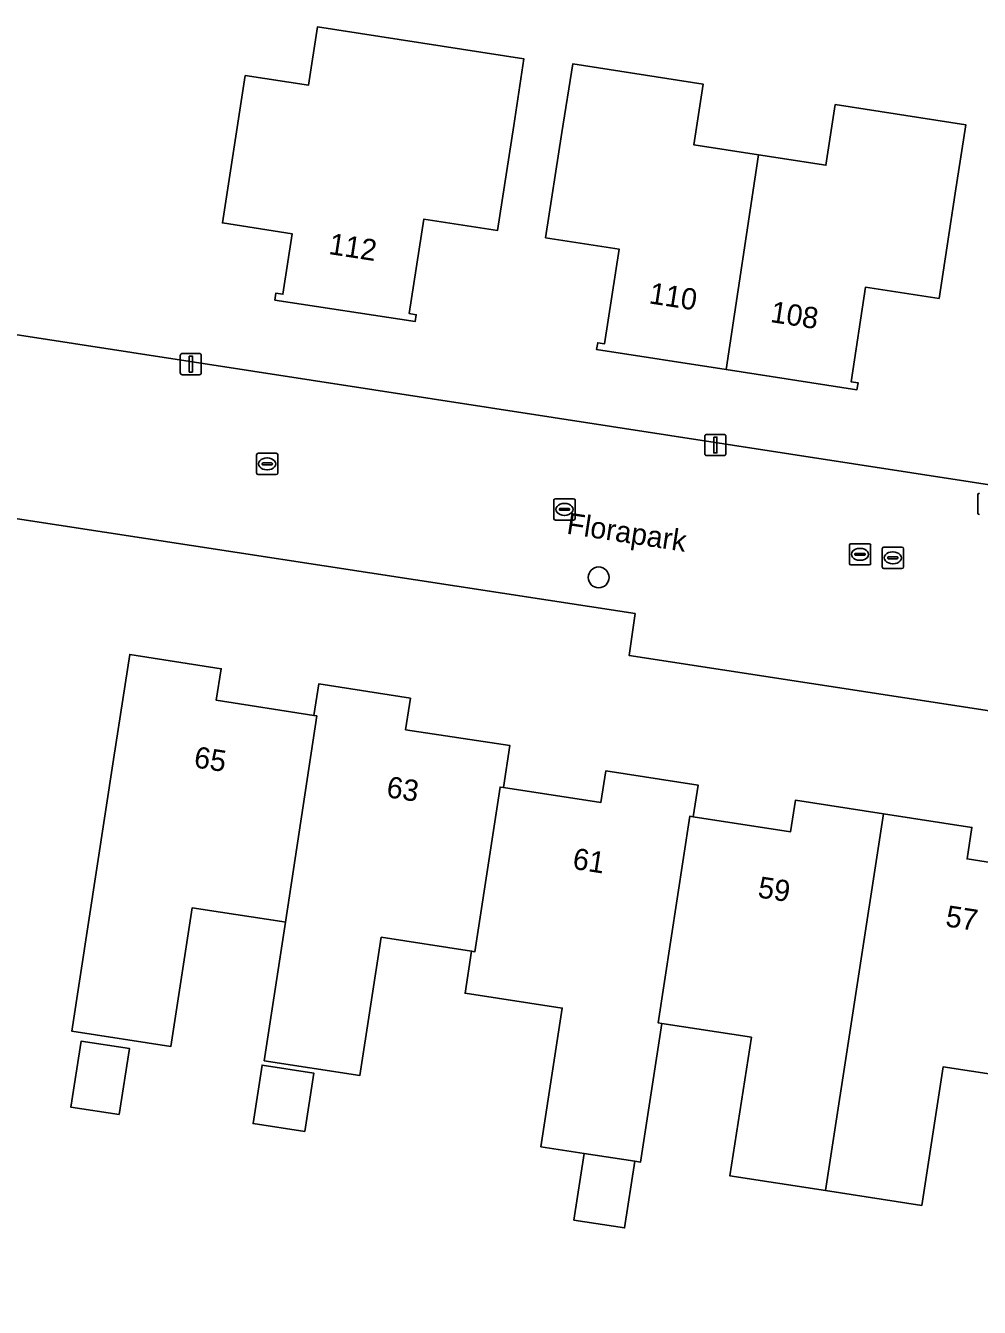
# Model space of a CAD drawing. Extents: x 161483 to 162250, y 379484 to 380833.
# Drawn here: x 161829.9 to 161874.7, y 380682.4 to 380742.6 of the extents above; entities that cross this region are included whole.
import ezdxf

# ---------------------------------------------------------------- set-up
doc = ezdxf.new("R2010")
doc.units = 0
for name, color, linetype in [('IMGEO_Boom', 7, 'Continuous'), ('IMGEO_Brandkraan', 7, 'Continuous'), ('IMGEO_Erf', 7, 'Continuous'), ('IMGEO_Kolk', 7, 'Continuous'), ('IMGEO_Lichtmast', 7, 'Continuous'), ('IMGEO_Openbare_ruimte_label', 7, 'Continuous'), ('IMGEO_Pand', 7, 'Continuous'), ('IMGEO_Pand_nummerreeks', 7, 'Continuous'), ('IMGEO_Rijbaan_lokaal_open', 7, 'Continuous'), ('IMGEO_Rioolput', 7, 'Continuous')]:
    doc.layers.add(name, color=color, linetype=linetype)

msp = doc.modelspace()

# ---------------------------------------------------------------- linework, layer by layer
at = {"layer": 'IMGEO_Boom'}
msp.add_circle((161856.794, 380716.676), 0.489, dxfattribs=at)
at = {"layer": 'IMGEO_Brandkraan'}
msp.add_line((161874.599, 380719.698), (161874.599, 380720.55), dxfattribs=at)
msp.add_lwpolyline([(161874.599, 380719.698), (161874.599, 380720.55)], dxfattribs=at)
for centre, start, end in [((161874.676, 380720.548), 91.55205, 178.44795), ((161874.676, 380720.548), 91.55205, 178.44795), ((161874.676, 380719.7), 181.55205, 268.44795), ((161874.676, 380719.7), 181.55205, 268.44795)]:
    msp.add_arc(centre, 0.0765, start, end, dxfattribs=at)
at = {"layer": 'IMGEO_Erf'}
for points in [[(161809.687, 380750), (161806.838, 380731.553), (161922.038, 380713.794), (161929.59, 380712.634), (161938.583, 380711.252), (161943.256, 380741.795), (161945.58, 380741.467)], [(161914.036, 380681.642), (161914.958, 380687.646), (161916.662, 380687.385), (161918.051, 380696.418), (161918.693, 380696.319), (161919.171, 380699.432), (161919.795, 380699.336), (161919.961, 380700.418), (161920.72, 380705.36), (161884.401, 380710.951), (161884.124, 380709.027), (161858.224, 380713.01), (161858.506, 380714.977), (161825.187, 380720.083)], [(161877.172, 380693.042), (161872.97, 380693.69), (161871.967, 380687.18), (161867.449, 380687.876), (161862.96, 380688.567), (161863.964, 380695.078), (161859.761, 380695.725), (161858.758, 380689.215), (161858.494, 380689.256), (161858.011, 380686.123), (161855.627, 380686.491), (161856.11, 380689.623), (161854.083, 380689.936), (161855.086, 380696.446), (161850.519, 380697.15), (161850.823, 380699.123), (161846.581, 380699.776), (161845.581, 380693.286), (161841.085, 380693.978), (161842.076, 380700.491), (161841.918, 380700.515), (161839.026, 380700.96), (161837.705, 380701.164), (161836.703, 380694.653), (161832.047, 380695.371), (161834.009, 380708.119), (161834.77, 380713.06), (161839.064, 380712.388), (161838.833, 380710.907), (161843.414, 380710.191), (161843.645, 380711.672), (161847.95, 380711), (161847.725, 380709.521), (161852.626, 380708.776), (161852.326, 380706.804), (161856.901, 380706.108), (161857.13, 380707.59), (161861.46, 380706.92), (161861.236, 380705.438), (161865.808, 380704.732), (161866.03, 380706.21), (161870.174, 380705.572), (161874.322, 380704.933), (161874.093, 380703.452), (161878.665, 380702.745)]]:
    msp.add_lwpolyline(points, dxfattribs=at)
for points in [[(161852.036, 380732.962), (161848.579, 380733.497), (161847.896, 380729.062), (161848.222, 380729.012), (161848.172, 380728.686), (161841.584, 380729.7), (161841.634, 380730.026), (161841.96, 380729.976), (161842.396, 380732.811), (161839.12, 380733.319), (161840.194, 380740.244), (161843.159, 380739.785), (161843.585, 380742.531), (161853.285, 380741.027), (161852.801, 380737.904)], [(161861.256, 380736.994), (161864.301, 380736.522), (161867.468, 380736.032), (161867.908, 380738.877), (161874.031, 380737.929), (161873.538, 380734.717), (161872.78, 380729.774), (161869.323, 380730.304), (161868.649, 380725.866), (161868.976, 380725.816), (161868.926, 380725.49), (161862.787, 380726.435), (161856.697, 380727.373), (161856.747, 380727.699), (161857.073, 380727.649), (161857.756, 380732.084), (161854.296, 380732.625), (161855.069, 380737.565), (161855.573, 380740.787), (161861.696, 380739.839)], [(161834.273, 380691.445), (161832.008, 380691.794), (161832.487, 380694.901), (161834.753, 380694.552)], [(161840.563, 380691.029), (161840.987, 380693.773), (161843.413, 380693.399), (161842.99, 380690.654)]]:
    msp.add_lwpolyline(points, close=True, dxfattribs=at)
at = {"layer": 'IMGEO_Kolk'}
for p, q in [((161840.723, 380721.58), (161840.723, 380722.432)), ((161840.798, 380722.506), (161841.65, 380722.506)), ((161841.724, 380722.432), (161841.724, 380721.58)), ((161840.982, 380722), (161840.982, 380722.012)), ((161841.42, 380721.963), (161841.022, 380721.963)), ((161841.025, 380722.049), (161841.423, 380722.049)), ((161841.211, 380722.286), (161841.236, 380722.286)), ((161841.466, 380722.012), (161841.466, 380722)), ((161841.65, 380721.506), (161840.798, 380721.506)), ((161841.234, 380721.726), (161841.209, 380721.726)), ((161854.687, 380719.443), (161854.687, 380720.295)), ((161854.762, 380720.369), (161855.614, 380720.369)), ((161855.175, 380720.149), (161855.2, 380720.149)), ((161855.688, 380720.295), (161855.688, 380719.443)), ((161855.614, 380719.369), (161854.762, 380719.369)), ((161854.946, 380719.863), (161854.946, 380719.875)), ((161855.384, 380719.826), (161854.986, 380719.826)), ((161854.989, 380719.912), (161855.387, 380719.912)), ((161855.198, 380719.589), (161855.173, 380719.589)), ((161855.43, 380719.875), (161855.43, 380719.863)), ((161868.567, 380717.333), (161868.567, 380718.185)), ((161868.642, 380718.259), (161869.494, 380718.259)), ((161869.568, 380718.185), (161869.568, 380717.333)), ((161868.826, 380717.753), (161868.826, 380717.765)), ((161869.264, 380717.716), (161868.866, 380717.716)), ((161868.869, 380717.802), (161869.267, 380717.802)), ((161869.055, 380718.039), (161869.08, 380718.039)), ((161869.31, 380717.765), (161869.31, 380717.753)), ((161869.494, 380717.259), (161868.642, 380717.259)), ((161869.078, 380717.479), (161869.053, 380717.479))]:
    msp.add_line(p, q, dxfattribs=at)
for points in [[(161840.723, 380721.58), (161840.723, 380722.432)], [(161840.798, 380722.506), (161841.65, 380722.506)], [(161841.724, 380722.432), (161841.724, 380721.58)], [(161841.65, 380721.506), (161840.798, 380721.506)], [(161854.687, 380719.443), (161854.687, 380720.295)], [(161854.762, 380720.369), (161855.614, 380720.369)], [(161855.688, 380720.295), (161855.688, 380719.443)], [(161855.614, 380719.369), (161854.762, 380719.369)], [(161868.567, 380717.333), (161868.567, 380718.185)], [(161868.642, 380718.259), (161869.494, 380718.259)], [(161869.568, 380718.185), (161869.568, 380717.333)], [(161869.494, 380717.259), (161868.642, 380717.259)]]:
    msp.add_lwpolyline(points, dxfattribs=at)
for centre, radius, start, end in [((161840.8, 380722.43), 0.0765, 91.55205, 178.44795), ((161840.8, 380722.43), 0.0765, 91.55205, 178.44795), ((161841.648, 380722.43), 0.0765, 1.55205, 88.44795), ((161841.648, 380722.43), 0.0765, 1.55205, 88.44795), ((161841.022, 380722.009), 0.0403, 85.87752, 175.75265), ((161841.019, 380721.999), 0.0366, 178.93798, 274.71019), ((161841.423, 380722.006), 0.043, 264.86636, 352.45326), ((161841.427, 380722.011), 0.0386, 1.73085, 96.63898), ((161840.8, 380721.582), 0.0765, 181.55205, 268.44795), ((161840.8, 380721.582), 0.0765, 181.55205, 268.44795), ((161841.648, 380721.582), 0.0765, 271.55205, 358.44795), ((161841.648, 380721.582), 0.0765, 271.55205, 358.44795), ((161854.764, 380720.293), 0.0765, 91.55205, 178.44795), ((161854.764, 380720.293), 0.0765, 91.55205, 178.44795), ((161855.612, 380720.293), 0.0765, 1.55205, 88.44795), ((161855.612, 380720.293), 0.0765, 1.55205, 88.44795), ((161854.764, 380719.445), 0.0765, 181.55205, 268.44795), ((161854.764, 380719.445), 0.0765, 181.55205, 268.44795), ((161854.986, 380719.872), 0.0403, 85.87752, 175.75265), ((161854.983, 380719.862), 0.0366, 178.93798, 274.71019), ((161855.387, 380719.869), 0.043, 264.86636, 352.45326), ((161855.391, 380719.874), 0.0386, 1.73085, 96.63898), ((161855.612, 380719.445), 0.0765, 271.55205, 358.44795), ((161855.612, 380719.445), 0.0765, 271.55205, 358.44795), ((161868.644, 380718.183), 0.0765, 91.55205, 178.44795), ((161868.644, 380718.183), 0.0765, 91.55205, 178.44795), ((161869.492, 380718.183), 0.0765, 1.55205, 88.44795), ((161869.492, 380718.183), 0.0765, 1.55205, 88.44795), ((161868.866, 380717.762), 0.0403, 85.87752, 175.75265), ((161868.863, 380717.752), 0.0366, 178.93798, 274.71019), ((161869.267, 380717.759), 0.043, 264.86636, 352.45326), ((161869.271, 380717.764), 0.0386, 1.73085, 96.63898), ((161868.644, 380717.335), 0.0765, 181.55205, 268.44795), ((161868.644, 380717.335), 0.0765, 181.55205, 268.44795), ((161869.492, 380717.335), 0.0765, 271.55205, 358.44795), ((161869.492, 380717.335), 0.0765, 271.55205, 358.44795)]:
    msp.add_arc(centre, radius, start, end, dxfattribs=at)
for centre, major_axis, ratio, start_param, end_param in [((161841.21, 380722.006), (-0.387, 0.002), 0.722429, 4.712389, 7.853982), ((161841.235, 380722.006), (-0.39, 0.002), 0.717154, 1.570796, 4.712389), ((161855.174, 380719.869), (-0.387, 0.002), 0.722429, 4.712389, 7.853982), ((161855.199, 380719.869), (-0.39, 0.002), 0.717154, 1.570796, 4.712389), ((161869.054, 380717.759), (-0.387, 0.002), 0.722429, 4.712389, 7.853982), ((161869.079, 380717.759), (-0.39, 0.002), 0.717154, 1.570796, 4.712389)]:
    msp.add_ellipse(centre, major_axis=major_axis, ratio=ratio, start_param=start_param, end_param=end_param, dxfattribs=at)
at = {"layer": 'IMGEO_Lichtmast'}
for p, q in [((161837.139, 380726.293), (161837.139, 380727.093)), ((161837.139, 380727.093), (161837.139, 380726.293)), ((161837.239, 380727.193), (161838.029, 380727.193)), ((161838.029, 380727.193), (161837.239, 380727.193)), ((161838.129, 380727.093), (161838.129, 380726.293)), ((161838.129, 380726.293), (161838.129, 380727.093)), ((161838.029, 380726.193), (161837.239, 380726.193)), ((161837.239, 380726.193), (161838.029, 380726.193)), ((161861.779, 380722.493), (161861.779, 380723.293)), ((161861.779, 380723.293), (161861.779, 380722.493)), ((161861.879, 380723.393), (161862.669, 380723.393)), ((161862.669, 380723.393), (161861.879, 380723.393)), ((161862.769, 380723.293), (161862.769, 380722.493)), ((161862.769, 380722.493), (161862.769, 380723.293)), ((161862.669, 380722.393), (161861.879, 380722.393)), ((161861.879, 380722.393), (161862.669, 380722.393))]:
    msp.add_line(p, q, dxfattribs=at)
for points in [[(161837.559, 380727.068), (161837.709, 380727.068), (161837.709, 380726.318), (161837.559, 380726.318), (161837.559, 380727.068)], [(161862.199, 380723.268), (161862.349, 380723.268), (161862.349, 380722.518), (161862.199, 380722.518), (161862.199, 380723.268)]]:
    msp.add_lwpolyline(points, dxfattribs=at)
for centre, start, end in [((161837.239, 380727.093), 90, 180), ((161837.239, 380727.093), 90, 180), ((161838.029, 380727.093), 0, 90), ((161838.029, 380727.093), 360, 90), ((161837.239, 380726.293), 180, 270), ((161837.239, 380726.293), 180, 270), ((161838.029, 380726.293), 270, 0), ((161838.029, 380726.293), 270, 0), ((161861.879, 380723.293), 90, 180), ((161861.879, 380723.293), 90, 180), ((161862.669, 380723.293), 0, 90), ((161862.669, 380723.293), 360, 90), ((161861.879, 380722.493), 180, 270), ((161861.879, 380722.493), 180, 270), ((161862.669, 380722.493), 270, 0), ((161862.669, 380722.493), 270, 0)]:
    msp.add_arc(centre, 0.1, start, end, dxfattribs=at)
at = {"layer": 'IMGEO_Pand'}
for points in [[(161839.12, 380733.319), (161842.396, 380732.811), (161841.96, 380729.976), (161841.634, 380730.026), (161841.584, 380729.7), (161848.172, 380728.686), (161848.222, 380729.012), (161847.896, 380729.062), (161848.579, 380733.497), (161852.036, 380732.962), (161852.801, 380737.904), (161853.285, 380741.027), (161843.585, 380742.531), (161843.159, 380739.785), (161840.194, 380740.244)], [(161864.301, 380736.522), (161861.256, 380736.994), (161861.696, 380739.839), (161855.573, 380740.787), (161855.069, 380737.565), (161854.296, 380732.625), (161857.756, 380732.084), (161857.073, 380727.649), (161856.747, 380727.699), (161856.697, 380727.373), (161862.787, 380726.435)], [(161864.301, 380736.522), (161862.787, 380726.435), (161868.926, 380725.49), (161868.976, 380725.816), (161868.649, 380725.866), (161869.323, 380730.304), (161872.78, 380729.774), (161873.538, 380734.717), (161874.031, 380737.929), (161867.908, 380738.877), (161867.468, 380736.032)], [(161843.414, 380710.191), (161838.833, 380710.907), (161839.064, 380712.388), (161834.77, 380713.06), (161834.009, 380708.119), (161832.047, 380695.371), (161836.703, 380694.653), (161837.705, 380701.164), (161839.026, 380700.96), (161841.918, 380700.515), (161842.076, 380700.491), (161843.549, 380710.17)], [(161852.166, 380706.828), (161852.326, 380706.804), (161852.626, 380708.776), (161847.725, 380709.521), (161847.95, 380711), (161843.645, 380711.672), (161843.414, 380710.191), (161843.549, 380710.17), (161842.076, 380700.491), (161841.085, 380693.978), (161845.581, 380693.286), (161846.581, 380699.776), (161850.823, 380699.123), (161850.981, 380699.099)], [(161861.076, 380705.463), (161861.236, 380705.438), (161861.46, 380706.92), (161857.13, 380707.59), (161856.901, 380706.108), (161852.326, 380706.804), (161852.166, 380706.828), (161850.981, 380699.099), (161850.823, 380699.123), (161850.519, 380697.15), (161855.086, 380696.446), (161854.083, 380689.936), (161856.11, 380689.623), (161858.494, 380689.256), (161858.758, 380689.215), (161859.761, 380695.725), (161859.594, 380695.751)], [(161859.761, 380695.725), (161863.964, 380695.078), (161862.96, 380688.567), (161867.449, 380687.876), (161870.174, 380705.572), (161866.03, 380706.21), (161865.808, 380704.732), (161861.236, 380705.438), (161861.076, 380705.463), (161859.594, 380695.751)], [(161878.665, 380702.745), (161874.093, 380703.452), (161874.322, 380704.933), (161870.174, 380705.572), (161867.449, 380687.876), (161871.967, 380687.18), (161872.97, 380693.69), (161877.172, 380693.042), (161877.33, 380693.018), (161878.824, 380702.72)], [(161834.273, 380691.445), (161834.753, 380694.552), (161832.487, 380694.901), (161832.008, 380691.794)], [(161843.413, 380693.399), (161840.987, 380693.773), (161840.563, 380691.029), (161842.99, 380690.654)], [(161858.494, 380689.256), (161856.11, 380689.623), (161855.627, 380686.491), (161858.011, 380686.123)]]:
    msp.add_lwpolyline(points, close=True, dxfattribs=at)
at = {"layer": 'IMGEO_Rijbaan_lokaal_open'}
msp.add_lwpolyline([(161922.038, 380713.794), (161806.838, 380731.553), (161805.542, 380723.095), (161813.7, 380721.85), (161821.311, 380720.678), (161821.36, 380720.995), (161825.235, 380720.397), (161825.187, 380720.083), (161858.506, 380714.977), (161858.224, 380713.01), (161884.124, 380709.027), (161884.401, 380710.951), (161920.72, 380705.36), (161928.91, 380704.1), (161937.319, 380702.795), (161938.583, 380711.252), (161929.59, 380712.634)], close=True, dxfattribs=at)
at = {"layer": 'IMGEO_Rioolput'}
for p, q in [((161870.109, 380717.168), (161870.109, 380718.02)), ((161870.184, 380718.094), (161871.036, 380718.094)), ((161870.368, 380717.588), (161870.368, 380717.6)), ((161870.411, 380717.637), (161870.809, 380717.637)), ((161870.597, 380717.874), (161870.622, 380717.874)), ((161870.852, 380717.6), (161870.852, 380717.588)), ((161871.11, 380718.02), (161871.11, 380717.168)), ((161871.036, 380717.094), (161870.184, 380717.094)), ((161870.806, 380717.551), (161870.408, 380717.551)), ((161870.62, 380717.314), (161870.595, 380717.314))]:
    msp.add_line(p, q, dxfattribs=at)
for points in [[(161870.109, 380717.168), (161870.109, 380718.02)], [(161870.184, 380718.094), (161871.036, 380718.094)], [(161871.11, 380718.02), (161871.11, 380717.168)], [(161871.036, 380717.094), (161870.184, 380717.094)]]:
    msp.add_lwpolyline(points, dxfattribs=at)
for centre, radius, start, end in [((161870.186, 380718.018), 0.0765, 91.55205, 178.44795), ((161870.186, 380718.018), 0.0765, 91.55205, 178.44795), ((161870.408, 380717.597), 0.0403, 85.87752, 175.75265), ((161870.405, 380717.587), 0.0366, 178.93798, 274.71019), ((161870.809, 380717.594), 0.043, 264.86636, 352.45326), ((161870.813, 380717.599), 0.0386, 1.73085, 96.63898), ((161871.034, 380718.018), 0.0765, 1.55205, 88.44795), ((161871.034, 380718.018), 0.0765, 1.55205, 88.44795), ((161870.186, 380717.17), 0.0765, 181.55205, 268.44795), ((161870.186, 380717.17), 0.0765, 181.55205, 268.44795), ((161871.034, 380717.17), 0.0765, 271.55205, 358.44795), ((161871.034, 380717.17), 0.0765, 271.55205, 358.44795)]:
    msp.add_arc(centre, radius, start, end, dxfattribs=at)
for centre, major_axis, ratio, start_param, end_param in [((161870.596, 380717.594), (-0.387, 0.002), 0.722429, 4.712389, 7.853982), ((161870.621, 380717.594), (-0.39, 0.002), 0.717154, 1.570796, 4.712389)]:
    msp.add_ellipse(centre, major_axis=major_axis, ratio=ratio, start_param=start_param, end_param=end_param, dxfattribs=at)

# ---------------------------------------------------------------- texts
at = {"layer": 'IMGEO_Openbare_ruimte_label'}
msp.add_text('Florapark', height=1, rotation=351.25384, dxfattribs=at).set_placement((161855.25, 380718.733))
at = {"layer": 'IMGEO_Pand_nummerreeks'}
for s, rotation, p in [('112', 351.24992, (161844.076, 380731.866)), ('110', 351.24644, (161859.121, 380729.549)), ('108', 351.24644, (161864.821, 380728.672)), ('65', 351.19364, (161837.744, 380707.761)), ('63', 351.19364, (161846.786, 380706.361)), ('61', 351.2452, (161855.529, 380702.993)), ('59', 351.24639, (161864.231, 380701.652)), ('57', 351.24639, (161873.046, 380700.295))]:
    msp.add_text(s, height=1, rotation=rotation, dxfattribs=at).set_placement(p)

doc.saveas('drawing.dxf')
